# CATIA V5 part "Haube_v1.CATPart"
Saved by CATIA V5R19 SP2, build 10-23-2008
Part number: Haube_v1
Bounding box of the stored display mesh (mm): x -51.374 to 198.051, y -134.661 to 142.033, z -7.5 to 38.894
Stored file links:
  D:\Catia_save\Konstruktion\Tank\Tankhaube\Haube_v1.CATPart
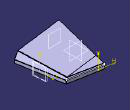
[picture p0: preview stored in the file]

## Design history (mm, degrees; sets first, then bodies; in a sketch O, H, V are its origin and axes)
SheetMetalParameters1: Thickness 1.5, BendRadius 1, KFactor 0.281235 {= log(min(100,max(20*SheetMetalParameters1.BendRadius,SheetMetalParameters1.Thickness)/SheetMetalParameters1.Thickness))/log(100)/2}, ReliefRadialLength 1, ReliefAxialLength 2, MinimumBendRadius 0
TTRSSet1
Body1 (main body)
  Plane1: type Offset, RefPlane yz-plane, Offset 178.104
  Sketch1 on Plane1, origin (178.104, 0, 0), H (0, 1, 0), V (0, 0, 1)
    line L1 (0, 4) -> (0, -2)
    point P1 (0, 4)
    coincidence: P1 V
    vertical: L1 V
  Plane2: type Angle, RefPlane Plane1, Direction Sketch1, Angle -10
  Sketch2 on Plane2, origin (177.559, 3.091, 0), H (0.1736, -0.9848, 0), V (0, 0, -1)
    line L1 (-109.5, 7.5) -> (109.5, 7.5)
    line L2 (109.5, 7.5) -> (109.5, -7.5)
    line L3 (109.5, -7.5) -> (-109.5, -7.5)
    line L4 (-109.5, -7.5) -> (-109.5, 7.5)
    length L2 = 15
    distance L4 L2 = 219
    horizontal: L1 H, L3 H
    vertical: L2 V, L4 V
    symmetry: L3 L1 H, L4 L2 V
  Wall1: Thickness 1.5, Profile Sketch2
  d_NewWallOnEdge1: NewWallOnEdge_Edge edge [face of Wall1 | face of Wall1], NewWallOnEdge_Length 152.4, NewWallOnEdge_HeightLimitOffset 0, NewWallOnEdge_WidthOffset1 0, NewWallOnEdge_WidthOffset2 0, NewWallOnEdge_Angle 110.592, NewWallOnEdge_BendRadiusValue 1 {= SheetMetalParameters1.BendRadius}, NewWallOnEdge_BendTable SheetMetalParameters1, KFacteur 0.281235 {= log(min(100,max(20*d_NewWallOnEdge1.Radius,SheetMetalParameters1.Thickness)/SheetMetalParameters1.Thickness))/log(100)/2}
  d_NewWallOnEdge2: NewWallOnEdge_Edge edge [face of Wall1 | face of Wall1], NewWallOnEdge_Length 20, NewWallOnEdge_HeightLimitOffset 0, NewWallOnEdge_WidthOffset1 0, NewWallOnEdge_WidthOffset2 0, NewWallOnEdge_Angle 145, NewWallOnEdge_BendRadiusValue 1 {= SheetMetalParameters1.BendRadius}, NewWallOnEdge_BendTable SheetMetalParameters1, KFacteur 0.281235 {= log(min(100,max(20*d_NewWallOnEdge2.Radius,SheetMetalParameters1.Thickness)/SheetMetalParameters1.Thickness))/log(100)/2}
  Sketch3 on face of d_NewWallOnEdge2, origin (120.5863, 21.2626, 85.738), H (-0.1736, 0.9848, 0), V (-0.5649, -0.0996, 0.8192)
    axis line L1 (-137.2887, -62.2069) -> (81.0187, -84.1453)
    point P1 (-137.2887, -62.2069)
    point P2 (81.0187, -84.1453)
    reference projected point E1 (-137.2887, -62.2069) from vertex [face of d_NewWallOnEdge2 | face of d_NewWallOnEdge2 | face of d_NewWallOnEdge2]
    reference projected line E2 (-136.0387, -94.1453) -> (79.7687, -94.1453) from edge [face of d_NewWallOnEdge2 | face of d_NewWallOnEdge2]
    reference projected line E3 (81.0187, -51.997) -> (81.0187, -83.9354) from edge [face of d_NewWallOnEdge2 | face of d_NewWallOnEdge2]
    line L2 (-137.2887, -62.2069) -> (81.0187, -62.2069)
    point P3 (-137.2887, -62.2069)
    line L3 (81.0187, -62.2069) -> (81.0187, -84.1453)
    line L4 (81.0187, -84.1453) -> (-137.2887, -62.2069)
    distance E2 P2 = 10
    coincidence: P1 E1, P2 E3, P3 L1, P3 P1
    horizontal: L2 H
    vertical: L3 V
    parallelism: L4 L1
  CutOut1: Direction Sketch3, EndLimit through (limit type 2), Orientation true, Profile Sketch3, StartLimit through (limit type 2)
  d_NewWallOnEdge3: NewWallOnEdge_Edge edge [face of CutOut1 | face of d_NewWallOnEdge2], NewWallOnEdge_Length 128, NewWallOnEdge_HeightLimit face of d_NewWallOnEdge1, NewWallOnEdge_HeightLimitOffset 0, NewWallOnEdge_WidthOffset1 0, NewWallOnEdge_WidthOffset2 0, NewWallOnEdge_Angle 126, NewWallOnEdge_BendRadiusValue 1 {= SheetMetalParameters1.BendRadius}, NewWallOnEdge_BendTable SheetMetalParameters1, KFacteur 0.281235 {= log(min(100,max(20*d_NewWallOnEdge3.Radius,SheetMetalParameters1.Thickness)/SheetMetalParameters1.Thickness))/log(100)/2}
  Plane3: type Offset, RefPlane zx-plane, Offset -104.745
  Sketch4 on face of d_NewWallOnEdge3, origin (0.1401, 2.144, 25.7107), H (0.9979, -0.0652, 0), V (-0.065, -0.9944, 0.0833)
    line L1 (-9.4177, -135.7292) -> (-15.1663, -87.7299)
    reference projected line E1 (-15.1663, -87.7299) -> (-42.4836, 140.361) from edge [face of d_NewWallOnEdge3 | face of d_NewWallOnEdge3]
    line L2 (-15.1663, -87.7299) -> (144.8894, -117.1187)
    point P3 (144.8894, -117.1187)
    line L3 (144.8894, -117.1187) -> (144.8651, -117.2515)
    line L4 (144.8651, -117.2515) -> (-9.4177, -135.7292)
    reference projected line E2 (-15.1663, -87.7299) -> (144.8894, -117.1187) from edge [face of d_NewWallOnEdge3 | face of d_NewWallOnEdge3]
    reference projected line E3 (144.8894, -117.1187) -> (184.5044, 98.6303) from edge [face of d_NewWallOnEdge3 | face of d_NewWallOnEdge3]
    reference projected line E4 (144.8894, -117.1187) -> (184.5044, 98.6303) from edge [face of d_NewWallOnEdge3 | face of d_NewWallOnEdge3]
    reference projected line E5 (150.2859, -120.0675) -> (-9.0741, -139.1532) from edge [face of d_NewWallOnEdge1 | face of d_NewWallOnEdge1]
    reference projected line E6 (150.2859, -120.0675) -> (-9.0741, -139.1532) from edge [face of d_NewWallOnEdge1 | face of d_NewWallOnEdge1]
    distance E6 L4 = 3.4406
    coincidence: L1 E1, L2 E2, L3 E3, P3 E4
    perpendicularity: L4 L1
    parallelism: E5 L4
  Wall2: Thickness 1.5, Profile Sketch4, ListTangentTo face of d_NewWallOnEdge3
  Sketch5 on face of d_NewWallOnEdge1, origin (25.6752, 137.3001, 0), H (-0.983, 0.1838, 0), V (0, 0, 1)
    line L1 (-134.7605, 15.9972) -> (25.7462, 14.4077)
    line L2 (25.7462, 14.4077) -> (25.7462, 9)
    line L3 (25.7462, 9) -> (-134.7605, 9)
    line L4 (-134.7605, 9) -> (-134.7605, 15.9972)
    reference projected line E1 (-134.7605, 7.5) -> (-134.7605, -7.5) from edge [face of d_NewWallOnEdge1 | face of d_NewWallOnEdge1]
    reference projected line E2 (25.7462, -7.5) -> (25.7462, 7.5) from edge [face of d_NewWallOnEdge1 | face of d_NewWallOnEdge1]
    reference projected line E3 (25.7462, 7.5) -> (-134.7605, 7.5) from edge [face of d_NewWallOnEdge1 | face of d_NewWallOnEdge1]
    reference projected line E4 (25.7462, 14.4077) -> (-129.6314, 15.9464) from edge [face of Wall2 | face of Wall2]
    distance L3 E3 = 1.5
    horizontal: L3 H
    vertical: L2 V, L4 V
    coincidence: L4 E1, L2 E2, L1 E4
